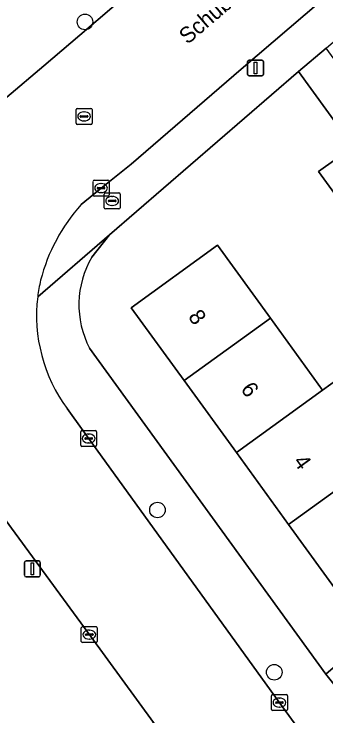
# Model space of a CAD drawing. Extents: x 159039 to 160102, y 381214 to 382524.
# Drawn here: x 159241.77 to 159261.33, y 381414.52 to 381458.57 of the extents above; entities that cross this region are included whole.
import ezdxf

# ---------------------------------------------------------------- set-up
doc = ezdxf.new("R2010")
doc.units = 0
for name, color, linetype in [('IMGEO_Boom', 7, 'Continuous'), ('IMGEO_Brandkraan', 7, 'Continuous'), ('IMGEO_Erf', 7, 'Continuous'), ('IMGEO_Groenvoorziening', 7, 'Continuous'), ('IMGEO_Kolk', 7, 'Continuous'), ('IMGEO_Lichtmast', 7, 'Continuous'), ('IMGEO_Openbare_ruimte_label', 7, 'Continuous'), ('IMGEO_Pand', 7, 'Continuous'), ('IMGEO_Pand_nummerreeks', 7, 'Continuous'), ('IMGEO_Rijbaan_lokaal_gesloten', 7, 'Continuous'), ('IMGEO_Rijbaan_lokaal_open', 7, 'Continuous'), ('IMGEO_Rioolput', 7, 'Continuous'), ('IMGEO_Voetpad_open', 7, 'Continuous')]:
    doc.layers.add(name, color=color, linetype=linetype)

msp = doc.modelspace()

# ---------------------------------------------------------------- linework, layer by layer
at = {"layer": 'IMGEO_Boom'}
for centre in [(159246.219, 381458.073), (159250.765, 381427.443), (159258.088, 381417.26)]:
    msp.add_circle(centre, 0.489, dxfattribs=at)
at = {"layer": 'IMGEO_Brandkraan'}
for p, q in [((159247.422, 381446.418), (159247.422, 381447.27)), ((159247.497, 381447.344), (159248.349, 381447.344)), ((159248.423, 381447.27), (159248.423, 381446.418)), ((159247.681, 381446.838), (159247.681, 381446.85)), ((159248.119, 381446.801), (159247.721, 381446.801)), ((159247.724, 381446.887), (159248.122, 381446.887)), ((159247.91, 381447.124), (159247.935, 381447.124)), ((159248.165, 381446.85), (159248.165, 381446.838)), ((159248.349, 381446.344), (159247.497, 381446.344)), ((159247.933, 381446.564), (159247.908, 381446.564))]:
    msp.add_line(p, q, dxfattribs=at)
for points in [[(159247.422, 381446.418), (159247.422, 381447.27)], [(159247.497, 381447.344), (159248.349, 381447.344)], [(159248.423, 381447.27), (159248.423, 381446.418)], [(159248.349, 381446.344), (159247.497, 381446.344)]]:
    msp.add_lwpolyline(points, dxfattribs=at)
for centre, radius, start, end in [((159247.499, 381447.268), 0.0765, 91.552, 178.448), ((159247.499, 381447.268), 0.0765, 91.552, 178.448), ((159248.347, 381447.268), 0.0765, 1.552, 88.448), ((159248.347, 381447.268), 0.0765, 1.552, 88.448), ((159247.721, 381446.847), 0.0403, 85.8775, 175.7526), ((159247.718, 381446.837), 0.0366, 178.938, 274.7102), ((159248.122, 381446.844), 0.043, 264.8664, 352.4533), ((159248.126, 381446.849), 0.0386, 1.7309, 96.639), ((159247.499, 381446.42), 0.0765, 181.552, 268.448), ((159247.499, 381446.42), 0.0765, 181.552, 268.448), ((159248.347, 381446.42), 0.0765, 271.552, 358.448), ((159248.347, 381446.42), 0.0765, 271.552, 358.448)]:
    msp.add_arc(centre, radius, start, end, dxfattribs=at)
for centre, major_axis, ratio, start_param, end_param in [((159247.909, 381446.844), (-0.387, 0.002), 0.722429, 4.712389, 7.853982), ((159247.934, 381446.844), (-0.39, 0.002), 0.717154, 1.570796, 4.712389)]:
    msp.add_ellipse(centre, major_axis=major_axis, ratio=ratio, start_param=start_param, end_param=end_param, dxfattribs=at)
at = {"layer": 'IMGEO_Erf'}
for points in [[(159267.473, 381439.572), (159264.199, 381444.09), (159260.87, 381448.683), (159263.028, 381450.246), (159259.615, 381454.955), (159247.758, 381444.719), (159246.645, 381443.315)], [(159246.508, 381437.599), (159261.321, 381417.145), (159276.058, 381429.872)]]:
    msp.add_lwpolyline(points, dxfattribs=at)
msp.add_lwpolyline([(159261.116, 381434.963), (159262.675, 381436.093), (159265.95, 381431.574), (159264.39, 381430.444), (159267.708, 381425.866), (159262.304, 381421.949), (159258.987, 381426.527), (159255.712, 381431.045), (159252.438, 381435.563), (159249.12, 381440.142), (159254.524, 381444.059), (159257.842, 381439.481)], close=True, dxfattribs=at)
msp.add_arc((159251.753, 381440.333), 5.915, 149.7255, 207.5285, dxfattribs=at)
at = {"layer": 'IMGEO_Groenvoorziening'}
msp.add_lwpolyline([(159250.118, 381413.782), (159250.219, 381413.888), (159250.505, 381414.099), (159246.576, 381419.509), (159240.1, 381428.34), (159237.479, 381431.85), (159235.186, 381435.587), (159221.031, 381420.621), (159227.014, 381407.964), (159223.85, 381406.468), (159224.961, 381404.117), (159222.267, 381402.843), (159224.548, 381401.543)], dxfattribs=at)
at = {"layer": 'IMGEO_Kolk'}
for p, q in [((159246.727, 381447.219), (159246.727, 381448.071)), ((159246.802, 381448.145), (159247.654, 381448.145)), ((159247.728, 381448.071), (159247.728, 381447.219)), ((159246.986, 381447.639), (159246.986, 381447.651)), ((159247.029, 381447.688), (159247.427, 381447.688)), ((159247.215, 381447.925), (159247.24, 381447.925)), ((159247.47, 381447.651), (159247.47, 381447.639)), ((159247.424, 381447.602), (159247.026, 381447.602)), ((159247.238, 381447.365), (159247.213, 381447.365)), ((159247.654, 381447.145), (159246.802, 381447.145)), ((159245.95, 381431.505), (159245.95, 381432.357)), ((159246.025, 381432.431), (159246.877, 381432.431)), ((159246.438, 381432.211), (159246.463, 381432.211)), ((159246.951, 381432.357), (159246.951, 381431.505)), ((159246.209, 381431.925), (159246.209, 381431.937)), ((159246.647, 381431.888), (159246.249, 381431.888)), ((159246.252, 381431.974), (159246.65, 381431.974)), ((159246.693, 381431.937), (159246.693, 381431.925)), ((159246.877, 381431.431), (159246.025, 381431.431)), ((159246.461, 381431.651), (159246.436, 381431.651)), ((159245.99, 381419.196), (159245.99, 381420.048)), ((159246.065, 381420.122), (159246.917, 381420.122)), ((159246.478, 381419.902), (159246.503, 381419.902)), ((159246.991, 381420.048), (159246.991, 381419.196)), ((159246.249, 381419.616), (159246.249, 381419.628)), ((159246.687, 381419.579), (159246.289, 381419.579)), ((159246.292, 381419.665), (159246.69, 381419.665)), ((159246.733, 381419.628), (159246.733, 381419.616)), ((159246.917, 381419.122), (159246.065, 381419.122)), ((159246.501, 381419.342), (159246.476, 381419.342)), ((159257.912, 381414.932), (159257.912, 381415.784)), ((159257.987, 381415.858), (159258.839, 381415.858)), ((159258.4, 381415.638), (159258.425, 381415.638)), ((159258.913, 381415.784), (159258.913, 381414.932)), ((159258.171, 381415.352), (159258.171, 381415.364)), ((159258.609, 381415.315), (159258.211, 381415.315)), ((159258.214, 381415.401), (159258.612, 381415.401)), ((159258.423, 381415.078), (159258.398, 381415.078)), ((159258.655, 381415.364), (159258.655, 381415.352)), ((159258.839, 381414.858), (159257.987, 381414.858))]:
    msp.add_line(p, q, dxfattribs=at)
for points in [[(159246.727, 381447.219), (159246.727, 381448.071)], [(159246.802, 381448.145), (159247.654, 381448.145)], [(159247.728, 381448.071), (159247.728, 381447.219)], [(159247.654, 381447.145), (159246.802, 381447.145)], [(159245.95, 381431.505), (159245.95, 381432.357)], [(159246.025, 381432.431), (159246.877, 381432.431)], [(159246.951, 381432.357), (159246.951, 381431.505)], [(159246.877, 381431.431), (159246.025, 381431.431)], [(159245.99, 381419.196), (159245.99, 381420.048)], [(159246.065, 381420.122), (159246.917, 381420.122)], [(159246.991, 381420.048), (159246.991, 381419.196)], [(159246.917, 381419.122), (159246.065, 381419.122)], [(159257.912, 381414.932), (159257.912, 381415.784)], [(159257.987, 381415.858), (159258.839, 381415.858)], [(159258.913, 381415.784), (159258.913, 381414.932)], [(159258.839, 381414.858), (159257.987, 381414.858)]]:
    msp.add_lwpolyline(points, dxfattribs=at)
for centre, radius, start, end in [((159246.804, 381448.069), 0.0765, 91.552, 178.448), ((159246.804, 381448.069), 0.0765, 91.552, 178.448), ((159247.652, 381448.069), 0.0765, 1.552, 88.448), ((159247.652, 381448.069), 0.0765, 1.552, 88.448), ((159247.026, 381447.648), 0.0403, 85.8775, 175.7526), ((159247.023, 381447.638), 0.0366, 178.938, 274.7102), ((159247.427, 381447.645), 0.043, 264.8664, 352.4533), ((159247.431, 381447.65), 0.0386, 1.7309, 96.639), ((159246.804, 381447.221), 0.0765, 181.552, 268.448), ((159246.804, 381447.221), 0.0765, 181.552, 268.448), ((159247.652, 381447.221), 0.0765, 271.552, 358.448), ((159247.652, 381447.221), 0.0765, 271.552, 358.448), ((159246.027, 381432.355), 0.0765, 91.552, 178.448), ((159246.027, 381432.355), 0.0765, 91.552, 178.448), ((159246.875, 381432.355), 0.0765, 1.552, 88.448), ((159246.875, 381432.355), 0.0765, 1.552, 88.448), ((159246.249, 381431.934), 0.0403, 85.8775, 175.7526), ((159246.246, 381431.924), 0.0366, 178.938, 274.7102), ((159246.65, 381431.931), 0.043, 264.8664, 352.4533), ((159246.654, 381431.936), 0.0386, 1.7309, 96.639), ((159246.027, 381431.507), 0.0765, 181.552, 268.448), ((159246.027, 381431.507), 0.0765, 181.552, 268.448), ((159246.875, 381431.507), 0.0765, 271.552, 358.448), ((159246.875, 381431.507), 0.0765, 271.552, 358.448), ((159246.067, 381420.046), 0.0765, 91.552, 178.448), ((159246.067, 381420.046), 0.0765, 91.552, 178.448), ((159246.915, 381420.046), 0.0765, 1.552, 88.448), ((159246.915, 381420.046), 0.0765, 1.552, 88.448), ((159246.289, 381419.625), 0.0403, 85.8775, 175.7526), ((159246.286, 381419.615), 0.0366, 178.938, 274.7102), ((159246.69, 381419.622), 0.043, 264.8664, 352.4533), ((159246.694, 381419.627), 0.0386, 1.7309, 96.639), ((159246.067, 381419.198), 0.0765, 181.552, 268.448), ((159246.067, 381419.198), 0.0765, 181.552, 268.448), ((159246.915, 381419.198), 0.0765, 271.552, 358.448), ((159246.915, 381419.198), 0.0765, 271.552, 358.448), ((159257.989, 381415.782), 0.0765, 91.552, 178.448), ((159257.989, 381415.782), 0.0765, 91.552, 178.448), ((159258.837, 381415.782), 0.0765, 1.552, 88.448), ((159258.837, 381415.782), 0.0765, 1.552, 88.448), ((159258.211, 381415.361), 0.0403, 85.8775, 175.7526), ((159258.208, 381415.351), 0.0366, 178.938, 274.7102), ((159258.612, 381415.358), 0.043, 264.8664, 352.4533), ((159258.616, 381415.363), 0.0386, 1.7309, 96.639), ((159257.989, 381414.934), 0.0765, 181.552, 268.448), ((159257.989, 381414.934), 0.0765, 181.552, 268.448), ((159258.837, 381414.934), 0.0765, 271.552, 358.448), ((159258.837, 381414.934), 0.0765, 271.552, 358.448)]:
    msp.add_arc(centre, radius, start, end, dxfattribs=at)
for centre, major_axis, ratio, start_param, end_param in [((159247.214, 381447.645), (-0.387, 0.002), 0.722429, 4.712389, 7.853982), ((159247.239, 381447.645), (-0.39, 0.002), 0.717154, 1.570796, 4.712389), ((159246.437, 381431.931), (-0.387, 0.002), 0.722429, 4.712389, 7.853982), ((159246.462, 381431.931), (-0.39, 0.002), 0.717154, 1.570796, 4.712389), ((159246.477, 381419.622), (-0.387, 0.002), 0.722429, 4.712389, 7.853982), ((159246.502, 381419.622), (-0.39, 0.002), 0.717154, 1.570796, 4.712389), ((159258.399, 381415.358), (-0.387, 0.002), 0.722429, 4.712389, 7.853982), ((159258.424, 381415.358), (-0.39, 0.002), 0.717154, 1.570796, 4.712389)]:
    msp.add_ellipse(centre, major_axis=major_axis, ratio=ratio, start_param=start_param, end_param=end_param, dxfattribs=at)
at = {"layer": 'IMGEO_Lichtmast'}
for p, q in [((159256.417, 381454.785), (159256.417, 381455.585)), ((159256.417, 381455.585), (159256.417, 381454.785)), ((159256.517, 381455.685), (159257.307, 381455.685)), ((159257.307, 381455.685), (159256.517, 381455.685)), ((159257.407, 381455.585), (159257.407, 381454.785)), ((159257.407, 381454.785), (159257.407, 381455.585)), ((159257.307, 381454.685), (159256.517, 381454.685)), ((159256.517, 381454.685), (159257.307, 381454.685)), ((159242.427, 381423.351), (159242.427, 381424.151)), ((159242.427, 381424.151), (159242.427, 381423.351)), ((159242.527, 381424.251), (159243.317, 381424.251)), ((159243.317, 381424.251), (159242.527, 381424.251)), ((159243.417, 381424.151), (159243.417, 381423.351)), ((159243.417, 381423.351), (159243.417, 381424.151)), ((159243.317, 381423.251), (159242.527, 381423.251)), ((159242.527, 381423.251), (159243.317, 381423.251))]:
    msp.add_line(p, q, dxfattribs=at)
for points in [[(159256.837, 381455.56), (159256.987, 381455.56), (159256.987, 381454.81), (159256.837, 381454.81), (159256.837, 381455.56)], [(159242.847, 381424.126), (159242.997, 381424.126), (159242.997, 381423.376), (159242.847, 381423.376), (159242.847, 381424.126)]]:
    msp.add_lwpolyline(points, dxfattribs=at)
for centre, start, end in [((159256.517, 381455.585), 90, 180), ((159256.517, 381455.585), 90, 180), ((159257.307, 381455.585), 0, 90), ((159257.307, 381455.585), 360, 90), ((159256.517, 381454.785), 180, 270), ((159256.517, 381454.785), 180, 270), ((159257.307, 381454.785), 270, 0), ((159257.307, 381454.785), 270, 0), ((159242.527, 381424.151), 90, 180), ((159242.527, 381424.151), 90, 180), ((159243.317, 381424.151), 0, 90), ((159243.317, 381424.151), 360, 90), ((159242.527, 381423.351), 180, 270), ((159242.527, 381423.351), 180, 270), ((159243.317, 381423.351), 270, 0), ((159243.317, 381423.351), 270, 0)]:
    msp.add_arc(centre, 0.1, start, end, dxfattribs=at)
at = {"layer": 'IMGEO_Pand'}
for points in [[(159264.199, 381444.09), (159266.356, 381445.654), (159263.028, 381450.246), (159260.87, 381448.683)], [(159257.842, 381439.481), (159254.524, 381444.059), (159249.12, 381440.142), (159252.438, 381435.563)], [(159261.116, 381434.963), (159257.842, 381439.481), (159252.438, 381435.563), (159255.712, 381431.045)], [(159261.116, 381434.963), (159255.712, 381431.045), (159258.987, 381426.527), (159264.39, 381430.444), (159265.95, 381431.574), (159262.675, 381436.093)], [(159264.39, 381430.444), (159258.987, 381426.527), (159262.304, 381421.949), (159267.708, 381425.866)]]:
    msp.add_lwpolyline(points, close=True, dxfattribs=at)
at = {"layer": 'IMGEO_Rijbaan_lokaal_gesloten'}
for points in [[(159245.979, 381446.609), (159247.332, 381447.733), (159249.106, 381449.157), (159256.003, 381455.11), (159266.909, 381464.432), (159272.134, 381469.012), (159277.501, 381473.611), (159272.211, 381479.825), (159269.659, 381477.653), (159250.208, 381460.939), (159245.889, 381457.245), (159243.638, 381455.319), (159241.329, 381453.344), (159235.381, 381448.161), (159233.403, 381442.507)], [(159234.788, 381436.235), (159235.186, 381435.587), (159237.479, 381431.85), (159240.1, 381428.34), (159246.576, 381419.509), (159250.505, 381414.099), (159254.07, 381409.287), (159259.21, 381402.243), (159267.246, 381391.102), (159269.773, 381387.639), (159277.386, 381377.231), (159281.568, 381371.476), (159283.858, 381368.081), (159291.452, 381356.822), (159293.118, 381357.931), (159293.293, 381358.079), (159293.373, 381358.142), (159294.192, 381358.793)], [(159273.822, 381394.288), (159272.056, 381396.709), (159266.652, 381404.115), (159260.931, 381411.92), (159258.606, 381415.092), (159258.439, 381415.32), (159246.108, 381432.406), (159245.1, 381433.81)]]:
    msp.add_lwpolyline(points, dxfattribs=at)
for centre, radius, start, end in [((159254.517, 381438.979), 11.451, 138.214, 165.4207), ((159253.164, 381439.622), 9.983, 167.0376, 173.0479), ((159253.03, 381439.648), 9.847, 173.1056, 216.3606)]:
    msp.add_arc(centre, radius, start, end, dxfattribs=at)
at = {"layer": 'IMGEO_Rijbaan_lokaal_open'}
msp.add_lwpolyline([(159309.494, 381458.306), (159309.289, 381458.131), (159308.398, 381457.371), (159294.831, 381445.789), (159294.662, 381445.645), (159293.7, 381444.812), (159280.226, 381433.226), (159279.48, 381432.596), (159276.058, 381429.872), (159261.321, 381417.145), (159263.262, 381414.719), (159296.875, 381443.481)], dxfattribs=at)
at = {"layer": 'IMGEO_Rioolput'}
for p, q in [((159245.663, 381451.719), (159245.663, 381452.571)), ((159245.738, 381452.645), (159246.59, 381452.645)), ((159246.664, 381452.571), (159246.664, 381451.719)), ((159245.922, 381452.139), (159245.922, 381452.151)), ((159246.36, 381452.102), (159245.962, 381452.102)), ((159245.965, 381452.188), (159246.363, 381452.188)), ((159246.151, 381452.425), (159246.176, 381452.425)), ((159246.406, 381452.151), (159246.406, 381452.139)), ((159246.59, 381451.645), (159245.738, 381451.645)), ((159246.174, 381451.865), (159246.149, 381451.865))]:
    msp.add_line(p, q, dxfattribs=at)
for points in [[(159245.663, 381451.719), (159245.663, 381452.571)], [(159245.738, 381452.645), (159246.59, 381452.645)], [(159246.664, 381452.571), (159246.664, 381451.719)], [(159246.59, 381451.645), (159245.738, 381451.645)]]:
    msp.add_lwpolyline(points, dxfattribs=at)
for centre, radius, start, end in [((159245.74, 381452.569), 0.0765, 91.552, 178.448), ((159245.74, 381452.569), 0.0765, 91.552, 178.448), ((159246.588, 381452.569), 0.0765, 1.552, 88.448), ((159246.588, 381452.569), 0.0765, 1.552, 88.448), ((159245.962, 381452.148), 0.0403, 85.8775, 175.7526), ((159245.959, 381452.138), 0.0366, 178.938, 274.7102), ((159246.363, 381452.145), 0.043, 264.8664, 352.4533), ((159246.367, 381452.15), 0.0386, 1.7309, 96.639), ((159245.74, 381451.721), 0.0765, 181.552, 268.448), ((159245.74, 381451.721), 0.0765, 181.552, 268.448), ((159246.588, 381451.721), 0.0765, 271.552, 358.448), ((159246.588, 381451.721), 0.0765, 271.552, 358.448)]:
    msp.add_arc(centre, radius, start, end, dxfattribs=at)
for centre, major_axis, ratio, start_param, end_param in [((159246.15, 381452.145), (-0.387, 0.002), 0.722429, 4.712389, 7.853982), ((159246.175, 381452.145), (-0.39, 0.002), 0.717154, 1.570796, 4.712389)]:
    msp.add_ellipse(centre, major_axis=major_axis, ratio=ratio, start_param=start_param, end_param=end_param, dxfattribs=at)
at = {"layer": 'IMGEO_Voetpad_open'}
for points in [[(159232.898, 381449.89), (159232.488, 381448.686), (159230.747, 381444.157), (159230.307, 381443.034), (159232.903, 381442.592), (159233.403, 381442.507), (159235.381, 381448.161), (159241.329, 381453.344), (159243.638, 381455.319), (159245.889, 381457.245), (159250.208, 381460.939), (159269.659, 381477.653), (159272.211, 381479.825), (159274.306, 381481.608), (159278.677, 381485.329), (159281.518, 381487.748), (159295.931, 381500), (159297.968, 381501.732), (159302.526, 381505.654), (159305.767, 381508.444), (159319.433, 381520.175)], [(159288.533, 381483.013), (159287.127, 381481.79), (159281.201, 381476.782), (159279.589, 381475.401), (159277.501, 381473.611), (159272.134, 381469.012), (159266.909, 381464.432), (159256.003, 381455.11), (159249.106, 381449.157), (159247.332, 381447.733), (159245.979, 381446.609)], [(159243.254, 381440.83), (159247.758, 381444.719), (159259.615, 381454.955), (159261.335, 381456.439), (159271.679, 381465.369), (159291.22, 381481.993)], [(159246.645, 381443.315), (159247.758, 381444.719), (159243.254, 381440.83)], [(159261.321, 381417.145), (159246.508, 381437.599)], [(159245.1, 381433.81), (159246.108, 381432.406), (159258.439, 381415.32), (159258.606, 381415.092), (159260.931, 381411.92), (159266.652, 381404.115), (159272.056, 381396.709), (159273.822, 381394.288), (159276.984, 381389.893), (159278.393, 381387.933), (159279.327, 381386.65), (159288.626, 381373.873), (159292.46, 381368.626), (159293.71, 381366.959), (159294.711, 381365.624), (159297.175, 381368.084), (159280.338, 381391.218), (159277.551, 381395.074), (159276.645, 381396.319), (159276.617, 381396.357), (159275.173, 381398.343), (159263.262, 381414.719), (159261.321, 381417.145)]]:
    msp.add_lwpolyline(points, dxfattribs=at)
msp.add_lwpolyline([(159267.307, 381448.194), (159266.284, 381449.613), (159263.349, 381453.661), (159261.335, 381456.439), (159259.615, 381454.955), (159263.028, 381450.246), (159266.356, 381445.654), (159269.63, 381441.136), (159272.905, 381436.617), (159273.189, 381436.226), (159274.961, 381437.475), (159273.401, 381439.628)], close=True, dxfattribs=at)
for centre, radius, start, end in [((159254.517, 381438.979), 11.451, 138.214, 165.4207), ((159251.753, 381440.333), 5.915, 149.7255, 207.5285), ((159253.164, 381439.622), 9.983, 167.0376, 173.0479), ((159253.03, 381439.648), 9.847, 173.1056, 216.3606)]:
    msp.add_arc(centre, radius, start, end, dxfattribs=at)

# ---------------------------------------------------------------- texts
at = {"layer": 'IMGEO_Openbare_ruimte_label'}
msp.add_text('Schubertlaan', height=1, rotation=40.5392, dxfattribs=at).set_placement((159252.65, 381456.625))
at = {"layer": 'IMGEO_Pand_nummerreeks'}
for s, p in [('8', (159252.649, 381439.567)), ('6', (159255.943, 381435.021)), ('4', (159259.239, 381430.473))]:
    msp.add_text(s, height=1, rotation=305.9299, dxfattribs=at).set_placement(p)

doc.saveas('drawing.dxf')
